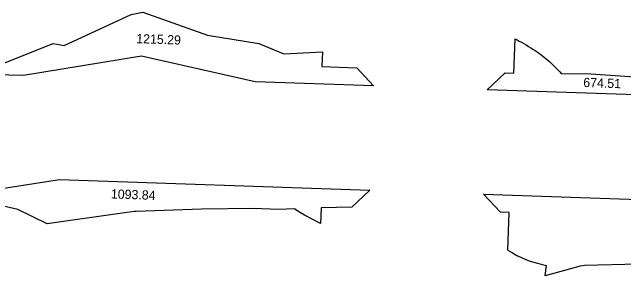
# Model space of a CAD drawing. Extents: x 2191309 to 2193046, y 863659 to 865133.
# Drawn here: x 2191516.5 to 2191715.3, y 864862.2 to 864947.9 of the extents above; entities that cross this region are included whole.
import ezdxf

# ---------------------------------------------------------------- set-up
doc = ezdxf.new("R2010")
doc.units = 0
for name, color, linetype in [('ANNOTATION', 7, 'Continuous'), ('D_Bridge_Abutment', 7, 'Continuous'), ('FRAME', 7, 'Continuous')]:
    doc.layers.add(name, color=color, linetype=linetype)

msp = doc.modelspace()

# ---------------------------------------------------------------- linework, layer by layer
at = {"layer": 'ANNOTATION'}
for p, q in [((2191558.49, 864933.56), (2191520.21, 864927.37)), ((2191595.51, 864925.29), (2191558.49, 864933.56)), ((2191520.21, 864927.37), (2191520.21, 864927.37)), ((2191633.94, 864923.97), (2191595.51, 864925.29)), ((2191498.38, 864888.35), (2191531.88, 864893.45)), ((2191531.88, 864893.45), (2191632.78, 864889.99)), ((2191669.75, 864888.72), (2191720.7, 864886.97))]:
    msp.add_line(p, q, dxfattribs=at)
for points in [[(2191555.19, 864947.2), (2191558.98, 864947.91), (2191579.98, 864940.48), (2191596.64, 864937.71), (2191604.78, 864934.36), (2191617.36, 864935.03), (2191617.2, 864930.2), (2191628.48, 864929.82), (2191633.94, 864923.97)], [(2191504.49, 864927.67), (2191529.85, 864937.74), (2191533.38, 864937.09), (2191555.19, 864947.2)], [(2191728.93, 864920.71), (2191670.92, 864922.7), (2191676.77, 864928.16), (2191679.61, 864928.06), (2191679.99, 864939.21)], [(2191520.21, 864927.37), (2191510.58, 864927.56), (2191504.49, 864927.67)], [(2191694.95, 864927.95), (2191704.62, 864927.87), (2191722.05, 864926.72), (2191729.29, 864923.7), (2191754.29, 864923.09), (2191759.38, 864922.96), (2191790.07, 864928.7), (2191804.37, 864925.92), (2191814.74, 864923.6), (2191825.14, 864921.45), (2191844.07, 864916.47)], [(2191632.78, 864889.99), (2191626.93, 864884.53), (2191616.91, 864884.21), (2191616.74, 864879.19)], [(2191616.74, 864879.19), (2191611.55, 864881.84), (2191609.63, 864882.92), (2191608.26, 864883.93), (2191603.05, 864883.77), (2191594.8, 864884), (2191578.03, 864883.86), (2191556.75, 864883.06), (2191556.26, 864883.09), (2191552.98, 864882.62), (2191527.84, 864879.01), (2191518.29, 864883.67), (2191503.11, 864887.23), (2191498.38, 864888.35)], [(2191677.63, 864870.46), (2191678.06, 864882.78), (2191675.21, 864882.87), (2191669.75, 864888.72)], [(2191727.97, 864869.78), (2191719.96, 864865.92), (2191702.48, 864865.46), (2191701.16, 864865.28), (2191689.72, 864862.16)], [(2191689.72, 864862.16), (2191690.13, 864865.54)]]:
    msp.add_lwpolyline(points, dxfattribs=at)
msp.add_arc((2191696.46, 864899.97), 35, 237.4643, 259.5928, dxfattribs=at)
msp.add_open_spline([(2191679.99, 864939.21), (2191681.61, 864938.43), (2191686.2, 864935.71), (2191690.55, 864932.53), (2191693.78, 864929.31), (2191694.95, 864927.95)], degree=3, dxfattribs=at)
at = {"layer": 'D_Bridge_Abutment'}
for p, q in [((2191670.92, 864922.7), (2191676.77, 864928.16)), ((2191669.75, 864888.72), (2191675.21, 864882.87))]:
    msp.add_line(p, q, dxfattribs=at)

# ---------------------------------------------------------------- texts
at = {"layer": 'FRAME'}
for s, p in [('1215.29', (2191556.8, 864937.85)), ('674.51', (2191702.09, 864923.59)), ('1093.84', (2191548.55, 864887.33))]:
    msp.add_text(s, height=3, rotation=358.0343, dxfattribs=at).set_placement(p)

doc.saveas('drawing.dxf')
